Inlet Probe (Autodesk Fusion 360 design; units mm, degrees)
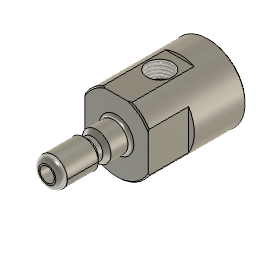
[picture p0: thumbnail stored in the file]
sketch "Sketch1" plane through (0, 0, 0) normal (1, 0, 0) x axis (0, 1, 0)
  line L1 (0, 0) -> (0, 6.35)
  line L2 (71.12, 16.51) -> (71.12, 0)
  line L3 (30.48, 6.35) -> (30.48, 16.51)
  line L4 (16.129, 6.35) -> (0, 6.35)
  line L5 (17.907, 4.572) -> (16.129, 6.35)
  line L6 (19.939, 4.572) -> (17.907, 4.572)
  line L7 (21.717, 6.35) -> (19.939, 4.572)
  line L8 (30.48, 6.35) -> (21.717, 6.35)
  line L9 (9.906, 4.572) -> (17.907, 4.572)
  line L10 (71.12, 0) -> (0, 0)
  line L11 (71.12, 16.51) -> (30.48, 16.51)
  line L12 (9.271, 6.35) -> (9.271, 14.9337)
  line L13 (21.717, 6.35) -> (16.129, 6.35)
  point P1 (0, 0)
  point P2 (0, 0)
  point P3 (71.12, 0)
  point P4 (71.12, 16.51)
  point P5 (30.48, 16.51)
  point P14 (9.271, 6.35)
  point P6 (30.48, 6.35)
  point P9 (17.907, 4.572)
  point P10 (19.939, 4.572)
  point P8 (16.129, 6.35)
  point P7 (0, 6.35)
  vertical L1
  vertical P1 P2
  perpendicular L1 L4
  perpendicular L1 L6
  perpendicular L5 L7
  perpendicular L3 L8
  parallel L6 L9
  equal L5 L7
  vertical L2
  horizontal P2 P3
  coincident P1 P2
  horizontal P4 P5
  coincident L4 P14
  perpendicular L4 L12
  vertical P5 P6
  dimension "d1" angle L5 L9 = 45
  dimension "d2" distance P9 P10 = 2.032
  dimension "d4" distance L4 L10 = 6.35
  dimension "d6" distance L10 L11 = 16.51
  dimension "d7" distance P1 L6 = 4.572
  dimension "d8" distance P1 L12 = 9.271
  dimension "d9" distance P8 L12 = 6.858
  dimension "d11" distance P1 P3 = 71.12
  dimension "d15" distance P6 P7 = 30.48
revolve "Revolve1" sketch "Sketch1" AlongAngle 360
fillet "Fillet1" radius 1.27
fillet "Fillet2" radius 2.54
chamfer "Chamfer1" distance 0.508
work_plane "WorkPlane1" RotateAngle 0
hole "Hole2" HoleDepth 10.16 (= "1 in - 0.6 in") HoleDiameter 7.9756 TipAngle 118
hole "Hole3" HoleDepth 49.53 HoleDiameter 6.35 TipAngle 118
sketch "Sketch5" plane through (0, 0, 0) normal (0, 1, 0) x axis (1, 0, 0)
work_plane "WorkPlane2" AlongDistance 17.145
sketch "Sketch7" plane through (0, 17.145, 0) normal (0, 1, 0) x axis (1, 0, 0)
  line L1 (0, -5.334) -> (0, 0)
  circle C1 centre (0, -5.334) radius 0.0635
  circle C2 centre (5.0729, -1.6483) radius 0.0635
  circle C3 centre (3.1352, 4.3153) radius 0.0635
  circle C4 centre (-3.1352, 4.3153) radius 0.0635
  circle C5 centre (-5.0729, -1.6483) radius 0.0635
  point P1 (0, 0)
  point P2 (0, -5.334)
  point P3 (0, 0)
  point P4 (0, -5.334)
  vertical P1 P2
  coincident P1 P3
  vertical L1
  coincident P2 P4
  dimension "d66" diameter C1 = 0.127
  dimension "d68" C-Pattern1-Angle = 360
split_face "SplitFace3"
split_face "SplitFace4"
split_face "SplitFace5"
split_face "SplitFace6"
split_face "SplitFace7"
sketch "Sketch8" plane through (0, 30.48, 0) normal (0, -1, 0) x axis (1, 0, 0)
  line L1 (-19.05, 12.7) -> (-13.97, 12.7)
  line L2 (-19.05, -12.7) -> (-19.05, 12.7)
  line L3 (-13.97, -12.7) -> (-19.05, -12.7)
  line L4 (-13.97, 12.7) -> (-13.97, -12.7)
  line L5 (19.05, 12.7) -> (13.97, 12.7)
  line L6 (19.05, -12.7) -> (19.05, 12.7)
  line L7 (13.97, -12.7) -> (19.05, -12.7)
  line L8 (13.97, 12.7) -> (13.97, -12.7)
  line L9 (6.35, 15.24) -> (-6.35, 15.24)
  line L10 (6.35, 17.78) -> (6.35, 15.24)
  line L11 (-6.35, 17.78) -> (6.35, 17.78)
  line L12 (-6.35, 15.24) -> (-6.35, 17.78)
  circle C1 centre (0, 0) radius 7.62
  circle C2 centre (0, 0) radius 16.002
  point P11 (0, 0)
  horizontal L1
  vertical L2
  horizontal L3
  vertical L4
  horizontal L5
  vertical L6
  horizontal L7
  vertical L8
  horizontal L9
  vertical L10
  horizontal L11
  vertical L12
  dimension "d71" distance L4 P11 = 13.97
  dimension "d72" distance L8 P11 = 13.97
extrude "Extrude3" cut sketch "Sketch8" profile of C2 L1 L2 L3 L4 L5 L6 L7 L8 against normal blind 17.78
sketch "Sketch9" plane through (0, 0, 16.51) normal (0, 0, 1) x axis (1, 0, 0)
  line L1 (-13.97, 30.48) -> (13.97, 30.48)
  line L2 (7.62, 58.3691) -> (-7.62, 58.3691)
  line L3 (7.62, 27.94) -> (7.62, 58.3691)
  line L4 (-7.62, 27.94) -> (7.62, 27.94)
  line L5 (-7.62, 58.3691) -> (-7.62, 27.94)
  circle C1 centre (0, 49.53) radius 13.97
  point P2 (0, 49.53)
  horizontal L2
  vertical L3
  horizontal L4
  vertical L5
  dimension "d73" diameter C1 = 27.94
  dimension "d82" distance P2 L1 = 19.05
hole "Hole1" HoleDepth 20.32 HoleDiameter 10.7188 TipAngle 118
split_face "SplitFace8"
extrude "Extrude5" cut sketch "Sketch8" profile of C2 L9 L10 L11 L12 against normal blind 27.94
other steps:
thread "Thread2" ThreadOffset 0 ThreadDepth 8.6081
thread "Thread1" ThreadOffset 0 ThreadDepth 0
